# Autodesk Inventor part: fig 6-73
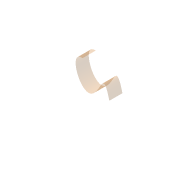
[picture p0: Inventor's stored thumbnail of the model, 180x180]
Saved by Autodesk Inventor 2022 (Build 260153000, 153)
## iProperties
Part Number: fig 6-73
Document SubType Name: Modeling
Created: 2002-12
Designer: deepak
Density: 1 g/cm^3
Material: Generic
Appearance: Default
Control State: 0
Master: False
Checked Out: False
Shininess: 64.0
Length Units: 11269
Angle Units: 11279
Time Units: 11290
Mass Units: 11283
Length Display Precision: 3
Angle Display Precision: 2
Compacted: True
Density: 0.0
Volumn: 0.0
Area: 0.0
PropertySet Name: Model Information
Author: deepak
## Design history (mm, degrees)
sketch "Sketch1"
  geometry: 5 further points
  constraints: 5 other
extrude_surface "ExtrusionSrf1" sketch "Sketch1" dims "d0" = 20, "d1" = 0
body "Srf1"
